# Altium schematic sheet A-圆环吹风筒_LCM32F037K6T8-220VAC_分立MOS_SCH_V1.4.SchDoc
size 469 x 355 mm; SheetNumber: 1; SheetTotal: 1
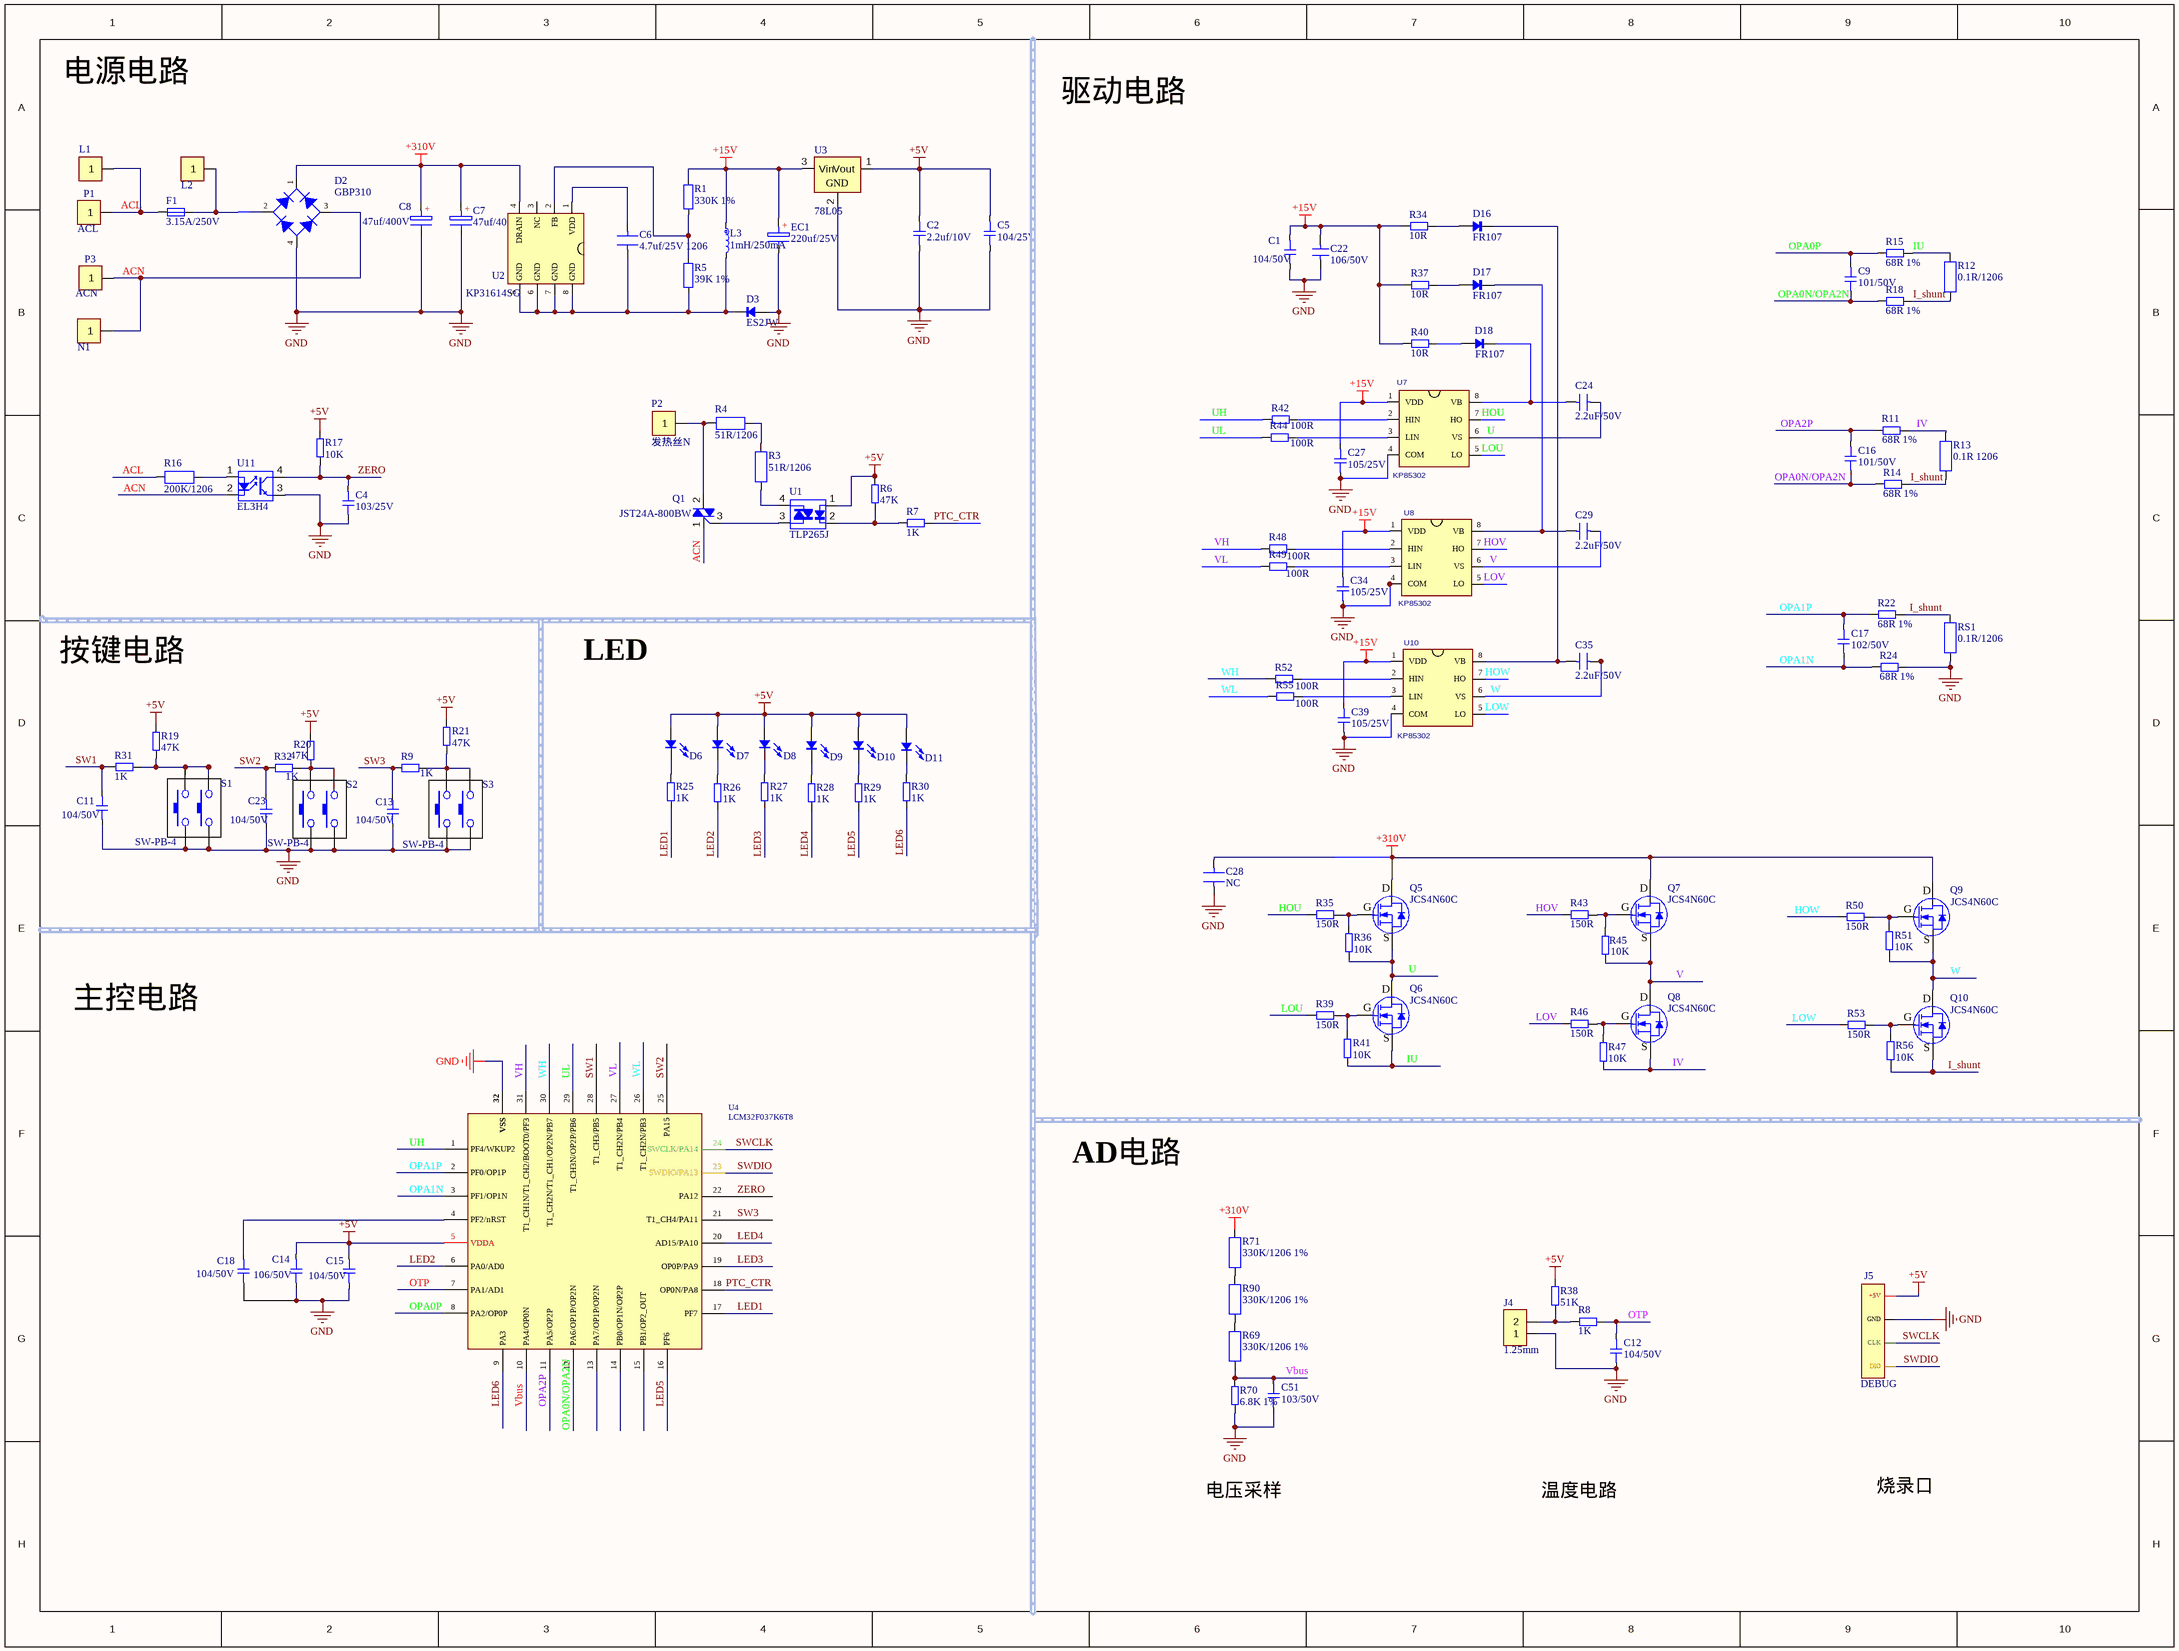
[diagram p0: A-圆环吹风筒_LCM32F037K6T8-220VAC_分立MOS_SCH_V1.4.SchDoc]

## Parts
C1  104/50V  [C0603]
C2  2.2uf/10V  [C0603]
C4  103/25V  [C0603]
C5  104/25V  [C0603]
C6  4.7uf/25V 1206  [C1206]
C7  47uf/400V  [CE5-13/26]
C8  47uf/400V  [CE5-13/26]
C9  101/50V  [C0603]
C11  104/50V  [C0603]
C12  104/50V  [C0603]
C13  104/50V  [C0603]
C14  106/50V  [C0603]
C15  104/50V  [C0603]
C16  101/50V  [C0603]
C17  102/50V  [C0603]
C18  104/50V  [C0603]
C22  106/50V  [C0805]
C23  104/50V  [C0603]
C24  2.2uF/50V  [C0805]
C27  105/25V  [C0603]
C28  NC  [C1206]
C29  2.2uF/50V  [C0805]
C34  105/25V  [C0603]
C35  2.2uF/50V  [C0805]
C39  105/25V  [C0603]
C51  103/50V  [C0603]
D2  GBP310  [D-KBP310]
D3  ES2JW  [SMB]
D6  LED  [LED-0603_B]  (value not drawn)
D7  LED  [LED-0603_B]  (value not drawn)
D8  LED  [LED-0603_B]  (value not drawn)
D9  LED  [LED-0603_B]  (value not drawn)
D10  LED  [LED-0603_B]  (value not drawn)
D11  LED  [LED-0603_B]  (value not drawn)
D16  FR107  [SOD-123]
D17  FR107  [SOD-123]
D18  FR107  [SOD-123]
EC1  220uf/25V  [CE2.54-5.5/11]
F1  3.15A/250V  [FUSE]
J4  1.25mm  [CON_1.25_2P]
J5  DEBUG  [PZ2.54-D-4P]
L1  PZPM1  [HOLD-16AWG]  (value not drawn)
L2  PZPM1  [HOLD-16AWG]  (value not drawn)
L3  1mH/250mA  [LD7*7-SMD]
N1  PZPM1  [HOLD-16AWG]  (value not drawn)
P1  ACL  [HOLD-16AWG]
P2  发热丝N  [HOLD-16AWG]
P3  ACN  [HOLD-16AWG]
Q1  JST24A-800BW  [TO220]
Q5  JCS4N60C  [TO-252-3L]
Q6  JCS4N60C  [TO-252-3L]
Q7  JCS4N60C  [TO-252-3L]
Q8  JCS4N60C  [TO-252-3L]
Q9  JCS4N60C  [TO-252-3L]
Q10  JCS4N60C  [TO-252-3L]
R1  330K 1%  [R0805]
R3  51R/1206  [R1206]
R4  51R/1206  [R1206]
R5  39K 1%  [R0805]
R6  47K  [R0603]
R7  1K  [R0603]
R8  1K  [R0603]
R9  1K  [R0603]
R11  68R 1%  [R0603]
R12  0.1R/1206  [R1206]
R13  0.1R 1206  [R1206]
R14  68R 1%  [R0603]
R15  68R 1%  [R0603]
R16  200K/1206  [R1206]
R17  10K  [R0603]
R18  68R 1%  [R0603]
R19  47K  [R0603]
R20  47K  [R0603]
R21  47K  [R0603]
R22  68R 1%  [R0603]
R24  68R 1%  [R0603]
R25  1K  [R0603]
R26  1K  [R0603]
R27  1K  [R0603]
R28  1K  [R0603]
R29  1K  [R0603]
R30  1K  [R0603]
R31  1K  [R0603]
R32  1K  [R0603]
R34  10R  [R0603]
R35  150R  [R0603]
R36  10K  [R0603]
R37  10R  [R0603]
R38  51K  [R0603]
R39  150R  [R0603]
R40  10R  [R0603]
R41  10K  [R0603]
R42  100R  [R0603]
R43  150R  [R0603]
R44  100R  [R0603]
R45  10K  [R0603]
R46  150R  [R0603]
R47  10K  [R0603]
R48  100R  [R0603]
R49  100R  [R0603]
R50  150R  [R0603]
R51  10K  [R0603]
R52  100R  [R0603]
R53  150R  [R0603]
R55  100R  [R0603]
R56  10K  [R0603]
R69  330K/1206 1%  [R1206]
R70  6.8K 1%  [R0603]
R71  330K/1206 1%  [R1206]
R90  330K/1206 1%  [R1206]
RS1  0.1R/1206  [R1206]
S1  SW-PB-4  [SW_2]
S2  SW-PB-4  [SW_2]
S3  SW-PB-4  [SW]
U1  TLP265J  [SO-4]
U2  KP31614SG  [SOP-8_L4.9-W3.9-P1.27-LS6.0-BL-PE3]
U3  78L05  [SOT89]
U4  LCM32F037K6T8  [LNCM-LQFP32-7X7-0.8]
U7  KP85302  [SOP-8]
U8  KP85302  [SOP-8]
U10  KP85302  [SOP-8]
U11  EL3H4  [SO-4-1.27]

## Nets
+5V: C2.1 C5.1 C14.1 C15.1 D6.1(A) D7.1(A) D8.1(A) D9.1(A) D10.1(A) D11.1(A) J5.1(+5V) R6.2 R17.2 R19.2 R20.2 R21.2 R38.2 U1.1(A) U3.1(Vout) U4.5(VDDA)
+15V: C1.1 C22.1 C27.1 C34.1 C39.1 EC1.1 L3.1 R1.2 R34.1 R37.1 R40.1 U3.3(Vin) U7.1(VDD) U8.1(VDD) U10.1(VDD)
+310V: C7.1 C8.1 C28.1 D2.1(DC+) Q5.2(D) Q7.2(D) Q9.2(D) R71.2 U2.4(DRAIN)
GND: C1.2 C2.2 C4.2 C5.2 C7.2 C8.2 C11.2 C12.2 C13.2 C14.2 C15.2 C18.2 C22.2 C23.2 C27.2 C28.2 C34.2 C39.2 C51.2 D2.4(DC-) D3.1(A) EC1.2 J4.1 J5.2(GND) R24.2 R70.2 RS1.1 S1.1 S1.2 S2.1 S2.2 S3.1 S3.2 U3.2(GND) U4.32(VSS) U7.4(COM) U8.4(COM) U10.4(COM) U11.3(E)
ACL: F1.1 L1.1 P1.1 R16.1
ACN: D2.3(AC2) N1.1 P3.1 Q1.1(A1) U11.2(K)
HOU: R35.1 U7.7(HO)
HOV: R43.1 U8.7(HO)
HOW: R50.1 U10.7(HO)
I_shunt: Q10.3(S) R12.1 R13.1 R14.2 R18.2 R22.2 R56.1 RS1.2
IU: Q6.3(S) R12.2 R15.2 R41.1
IV: Q8.3(S) R11.2 R13.2 R47.1
LED1: R25.1 U4.17(PF7)
LED2: R26.1 U4.6(PA0/AD0)
LED3: R27.1 U4.19(OP0P/PA9)
LED4: R28.1 U4.20(AD15/PA10)
LED5: R29.1 U4.16(PF6)
LED6: R30.1 U4.9(PA3)
LOU: R39.1 U7.5(LO)
LOV: R46.1 U8.5(LO)
LOW: R53.1 U10.5(LO)
OPA0N/OPA2N: C9.2 C16.2 R14.1 R18.1 U4.12(PA6/OP1P/OP2N)
OPA0P: C9.1 R15.1 U4.8(PA2/OP0P)
OPA1N: C17.2 R24.1 U4.3(PF1/OP1N)
OPA1P: C17.1 R22.1 U4.2(PF0/OP1P)
OPA2P: C16.1 R11.1 U4.11(PA5/OP2P)
OTP: C12.1 R8.1 U4.7(PA1/AD1)
PTC_CTR: R7.2 U4.18(OP0N/PA8)
SW1: C11.1 R31.2 U4.28(T1_CH3/PB5)
SW2: C23.1 R32.1 U4.25(PA15)
SW3: C13.1 R9.1 U4.21(T1_CH4/PA11)
SWCLK: J5.3(CLK) U4.24(SWCLK/PA14)
SWDIO: J5.4(DIO) U4.23(SWDIO/PA13)
U: C24.2 Q5.3(S) Q6.2(D) R36.1 U7.6(VS)
UH: R42.1 U4.1(PF4/WKUP2)
UL: R44.1 U4.29(T1_CH3N/OP2P/PB6)
V: C29.2 Q7.3(S) Q8.2(D) R45.1 U8.6(VS)
Vbus: C51.1 R69.1 R70.1 U4.10(PA4/OP0N)
VH: R48.1 U4.31(T1_CH1N/T1_CH2/BOOT0/PF3)
VL: R49.1 U4.27(T1_CH2N/PB4)
W: C35.2 Q9.3(S) Q10.2(D) R51.1 U10.6(VS)
WH: R52.1 U4.30(T1_CH2N/T1_CH1/OP2N/PB7)
WL: R55.1 U4.26(T1_CH2N/PB3)
ZERO: C4.1 R17.1 U4.22(PA12) U11.4(C)
NetC6_1: C6.1 U2.1(VDD)
NetC6_2: C6.2 D3.2(K) L3.2 R5.1 U2.5(GND) U2.6(GND) U2.7(GND) U2.8(GND)
NetC18_1: C18.1 U4.4(PF2/nRST)
NetC24_1: C24.1 D18.2(K) U7.8(VB)
NetC29_1: C29.1 D17.2(K) U8.8(VB)
NetC35_1: C35.1 D16.2(K) U10.8(VB)
NetD2_2: D2.2(AC1) F1.2 L2.1
NetD6_2: D6.2(K) R25.2
NetD7_2: D7.2(K) R26.2
NetD8_2: D8.2(K) R27.2
NetD9_2: D9.2(K) R28.2
NetD10_2: D10.2(K) R29.2
NetD11_2: D11.2(K) R30.2
NetD16_1: D16.1(A) R34.2
NetD17_1: D17.1(A) R37.2
NetD18_1: D18.1(A) R40.2
NetJ4_2: J4.2 R8.2 R38.1
NetP2_1: P2.1 Q1.2(A2) R4.1
NetQ1_3: Q1.3(G) U1.3(E)
NetQ5_1: Q5.1(G) R35.2 R36.2
NetQ6_1: Q6.1(G) R39.2 R41.2
NetQ7_1: Q7.1(G) R43.2 R45.2
NetQ8_1: Q8.1(G) R46.2 R47.2
NetQ9_1: Q9.1(G) R50.2 R51.2
NetQ10_1: Q10.1(G) R53.2 R56.2
NetR1_1: R1.1 R5.2 U2.2(FB)
NetR3_1: R3.1 U1.4(C)
NetR3_2: R3.2 R4.2
NetR6_1: R6.1 R7.1 U1.2(K)
NetR9_2: R9.2 R21.1 S3.3 S3.4
NetR16_2: R16.2 U11.1(A)
NetR19_1: R19.1 R31.1 S1.3 S1.4
NetR20_1: R20.1 R32.2 S2.3 S2.4
NetR42_2: R42.2 U7.2(HIN)
NetR44_2: R44.2 U7.3(LIN)
NetR48_2: R48.2 U8.2(HIN)
NetR49_2: R49.2 U8.3(LIN)
NetR52_2: R52.2 U10.2(HIN)
NetR55_2: R55.2 U10.3(LIN)
NetR69_2: R69.2 R90.1
NetR71_1: R71.1 R90.2

Not connected (* = marked no-connect by the designer): U2 3(NC); U4 13(PA7/OP1P/OP2N) 14(PB0/OP1N/OP2P) 15(PB1/OP2_OUT)

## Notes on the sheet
- 电源电路
- 驱动电路
- 按键电路
- LED
- 主控电路
- AD电路
- 烧录口
- 电压采样
- 温度电路

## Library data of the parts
C1 C2 C4 C5 C9 C11-C18 C23 C27 C34 C39 C51 = A_CAP_6: 0603; BOM名称: 无极性贴片电容
C6 C28 = A_CAP_12: 1206/1808; BOM名称: 无极性贴片电容
C7 C8 EC1 = A_CAP_CE_DIP: 直插电解电容
C22 C24 C29 C35 = A_CAP_8: 0805; BOM名称: 无极性贴片电容
D2 = BRIDGE: 整流桥
D3 = DIO: 二极管/高效率/通用
D6-D11 = DIO_LED_SMD: 贴片LED
D16-D18 = DIO_RD: 整流二极管
F1 = FUSE1: 一次性保险丝; C2839769: 8A 250V
J4 = CON2: Connector
J5 = PZ4-SHAOLU: 烧录口; BOM名称: 4P连接器
L1 L2 N1 P1-P3 = PZPM1: 排针排母
L3 = INDUCTOR: 贴片电感; BOM名称: 小功率贴片电感
Q1 = D_SCR_SH: 双向可控硅
Q5-Q10 = D_MOS_N-2D/: N沟道; BOM名称: N沟道场效应管
R1 R5 = A_RES_8: 0805; BOM名称: 贴片电阻
R3 R4 R12 R13 R16 R69 R71 R90 RS1 = A_RES_12: 1206; BOM名称: 贴片电阻
R6-R9 R11 R14 R15 R17-R22 R24-R32 R34-R53 R55 R56 R70 = A_RES_6: 0603; BOM名称: 贴片电阻
U1 = OC_ELM3052: 光耦-可控硅信号输出
U2 = IC_DY_KP3114: 功率电子开关/BUCK_DC-DC
U3 = LDO_2D/: BUCK_DC-DC; BOM名称: 线性稳压芯片
U4 = MCU_通用_32位_F038_A1: K8T8
U7 U8 U10 = IC_栅驱_KP85302: 650V 300mA/600mA
U11 = OC_EL357N: 光耦-光电晶体管输出; BOM名称: 线性光耦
